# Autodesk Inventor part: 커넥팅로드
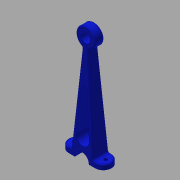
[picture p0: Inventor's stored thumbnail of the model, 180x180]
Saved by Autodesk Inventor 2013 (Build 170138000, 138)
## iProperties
Created: 2017-05
Part Number: 커넥팅로드
Material: 강철, 탄소
Document SubType Name: Modeling
Designer: mduedu
Density: 7.87 g/cm^3
Mass: 120.522 g
Surface Area: 85.3879 cm^2
Volume: 15.3141 cm^3
Author: mduedu
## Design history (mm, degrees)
sketch "스케치1"
  geometry: L1 (-22.5, 0)-(22.5, 0); L2 (22.5, 0)-(22.5, 5); L3 (-22.5, 5)-(-22.5, 0); L4 (-11.352, 5)-(-3, 100.461); L5 (0, 110)-(0, 0); L6 (11.352, 5)-(3, 100.461); L7 (22.5, 5)-(11.352, 5); L8 (-11.352, 5)-(-22.5, 5); C1 r 5 at (0, 110); A1 r 10 centre (0, 110) between (3, 100.461) and (-3, 100.461); 1 further point
  constraints: 16 end point, 4 parallel, 2 centre point, 2 coincident, 2 point on circle, 2 symmetric about line, 1 horizontal, 1 midpoint, 1 perpendicular, 1 vertical alignment
  dimensions: "d0" = 5 distance of L1.end L2.end; "d2" = 45 distance of L1.start L1.end; "d3" = 20 diameter of A1; "d4" = 10 diameter of C1; "d5" = 110 distance from line of L1 L5.start; "d6" = 5 deg angle of L5 L4; "d7" = 3 distance from line of L4.end L5
extrude "돌출1" new body sketch "스케치1" distance "d8" = 8.5; taper "d9" = 0 deg
sketch "스케치2"
  geometry: C1 r 7.5 at (0, 0); 1 further point
  constraints: 1 centre point, 1 coincident
  dimensions: "d10" = 15 diameter of C1
extrude "돌출2" cut sketch "스케치2" stored distance "d11" = 8.5; taper "d12" = 0 deg
sketch "스케치3"
  geometry: L1 (-3, 100.461)-(-11.352, 5) reference; L2 (11.352, 5)-(3, 100.461) reference; L3 (-3.154, 64.276)-(-6.975, 20.61); L4 (6.975, 20.61)-(3.154, 64.276); A1 r 3.166 centre (0, 64) between (3.154, 64.276) and (-3.154, 64.276); A2 r 7.001 centre (0, 20) between (-6.975, 20.61) and (6.975, 20.61); 1 further point
  constraints: 4 end point, 4 point on circle, 4 tangent, 2 centre point, 2 parallel, 1 vertical alignment
  dimensions: "d15" = 3 distance between parallel lines of L2 L4; "d16" = 44 distance of A2.centre A1.centre; "d17" = 20 distance of A2.centre point (0, 0)
extrude "돌출3" cut sketch "스케치3" stored distance "d18" = 8.5; taper "d19" = 0 deg
fillet "모깎기1" dims "d20" = 2
fillet "모깎기2" dims "d21" = 2
feature "면 기울기1" dims angle "d22" = 2 deg
fillet "모깎기3"
fillet "모깎기4"
fillet "모깎기5" dims "d28" = 1
sketch "스케치5"
  geometry: 3 further points
  constraints: 2 horizontal alignment
  dimensions: "d29" = 16.5 distance of point (-2.364, -7.36) point (14.136, -7.36); "d30" = 16.5 distance of point (30.636, -7.36) point (14.136, -7.36) (= d29)
sketch "스케치6"
  geometry: 2 further points
  constraints: 2 other
hole "구멍1" sketch "스케치6" at (-29.684, -7.36), (3.316, -7.36) diameter "d31" = 3.4; stored, may be unused: countersink angle "d35" = 90 deg, drill point angle "d37" = 0 deg; dims "d32" = 6, "d33" = 4, "d34" = 2, "d36" = 8
node "솔리드1"
mirror "대칭1"
other parameters: "d13" = 4, "d14" = 4
